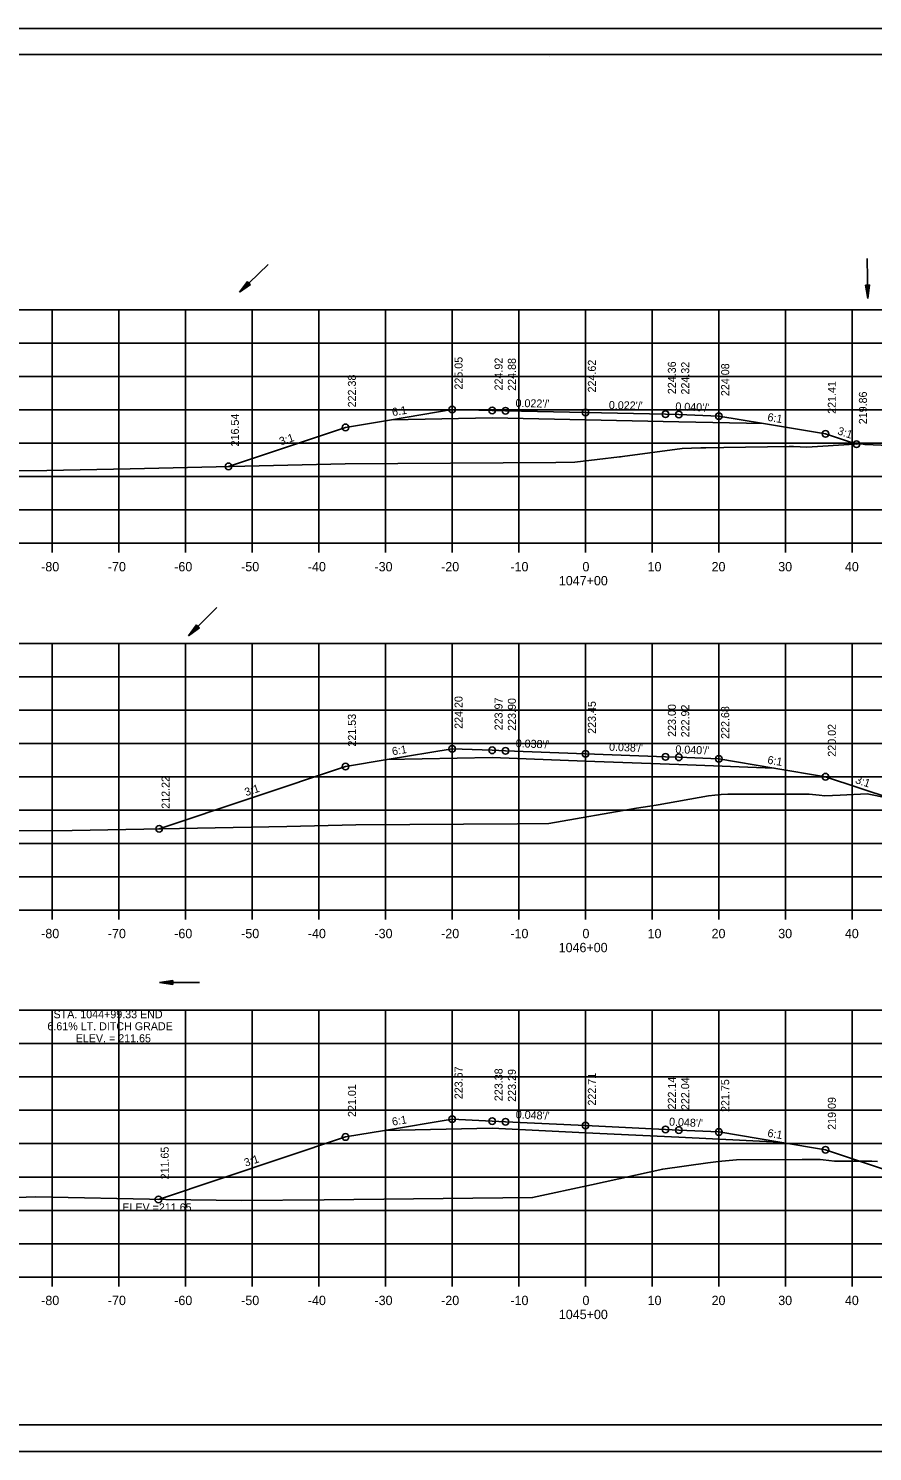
# Model space of a CAD drawing. Extents: x 1386544 to 1388153, y 379785 to 390999.
# Drawn here: x 1387276.1 to 1387402.7, y 387158.9 to 387372.2 of the extents above; entities that cross this region are included whole.
import ezdxf

# ---------------------------------------------------------------- set-up
doc = ezdxf.new("R2010")
doc.units = 0
for name, color, linetype in [('R_Alt Surface', 7, 'Continuous'), ('R_Axis', 7, 'Continuous'), ('R_Axis Annot', 7, 'Continuous'), ('R_Border', 7, 'Continuous'), ('R_Exist Surface', 7, 'Continuous'), ('R_Fin Surface', 7, 'Continuous'), ('R_Grid', 7, 'Continuous'), ('R_No Plot', 7, 'Continuous'), ('R_Water', 7, 'Continuous'), ('R_Xsect Elev', 7, 'Continuous'), ('R_Xsect Slope', 7, 'Continuous')]:
    doc.layers.add(name, color=color, linetype=linetype)

msp = doc.modelspace()

# ---------------------------------------------------------------- linework, layer by layer
at = {"layer": 'R_Alt Surface'}
for points in [[(1387330.59, 387313.54), (1387345.68, 387313.84), (1387359.68, 387313.54), (1387373.68, 387313.24), (1387386.38, 387312.97)], [(1387329.94, 387262.58), (1387345.68, 387262.9), (1387359.68, 387262.37), (1387373.68, 387261.85), (1387387.95, 387261.31)], [(1387329.51, 387206.98), (1387345.68, 387207.31), (1387359.68, 387206.63), (1387373.68, 387205.96), (1387388.81, 387205.24)]]:
    msp.add_lwpolyline(points, dxfattribs=at)
at = {"layer": 'R_Axis'}
for p, q in [((1387209.68, 387295.01), (1387509.68, 387295.01)), ((1387279.68, 387293.61), (1387279.68, 387295.01)), ((1387289.68, 387293.61), (1387289.68, 387295.01)), ((1387299.68, 387293.61), (1387299.68, 387295.01)), ((1387309.68, 387293.61), (1387309.68, 387295.01)), ((1387319.68, 387293.61), (1387319.68, 387295.01)), ((1387329.68, 387293.61), (1387329.68, 387295.01)), ((1387339.68, 387293.61), (1387339.68, 387295.01)), ((1387349.68, 387293.61), (1387349.68, 387295.01)), ((1387359.68, 387293.61), (1387359.68, 387295.01)), ((1387369.68, 387293.61), (1387369.68, 387295.01)), ((1387379.68, 387293.61), (1387379.68, 387295.01)), ((1387389.68, 387293.61), (1387389.68, 387295.01)), ((1387399.68, 387293.61), (1387399.68, 387295.01)), ((1387209.68, 387240.01), (1387509.68, 387240.01)), ((1387279.68, 387238.61), (1387279.68, 387240.01)), ((1387289.68, 387238.61), (1387289.68, 387240.01)), ((1387299.68, 387238.61), (1387299.68, 387240.01)), ((1387309.68, 387238.61), (1387309.68, 387240.01)), ((1387319.68, 387238.61), (1387319.68, 387240.01)), ((1387329.68, 387238.61), (1387329.68, 387240.01)), ((1387339.68, 387238.61), (1387339.68, 387240.01)), ((1387349.68, 387238.61), (1387349.68, 387240.01)), ((1387359.68, 387238.61), (1387359.68, 387240.01)), ((1387369.68, 387238.61), (1387369.68, 387240.01)), ((1387379.68, 387238.61), (1387379.68, 387240.01)), ((1387389.68, 387238.61), (1387389.68, 387240.01)), ((1387399.68, 387238.61), (1387399.68, 387240.01)), ((1387209.68, 387185.01), (1387509.68, 387185.01)), ((1387279.68, 387183.61), (1387279.68, 387185.01)), ((1387289.68, 387183.61), (1387289.68, 387185.01)), ((1387299.68, 387183.61), (1387299.68, 387185.01)), ((1387309.68, 387183.61), (1387309.68, 387185.01)), ((1387319.68, 387183.61), (1387319.68, 387185.01)), ((1387329.68, 387183.61), (1387329.68, 387185.01)), ((1387339.68, 387183.61), (1387339.68, 387185.01)), ((1387349.68, 387183.61), (1387349.68, 387185.01)), ((1387359.68, 387183.61), (1387359.68, 387185.01)), ((1387369.68, 387183.61), (1387369.68, 387185.01)), ((1387379.68, 387183.61), (1387379.68, 387185.01)), ((1387389.68, 387183.61), (1387389.68, 387185.01)), ((1387399.68, 387183.61), (1387399.68, 387185.01))]:
    msp.add_line(p, q, dxfattribs=at)
at = {"layer": 'R_Border'}
for p, q in [((1387201.68, 387368.3), (1387517.86, 387368.3)), ((1387354.2, 387368.04), (1387354.2, 387368.04)), ((1387354.2, 387368.04), (1387354.2, 387368.04)), ((1387517.86, 387162.84), (1387201.68, 387162.84))]:
    msp.add_line(p, q, dxfattribs=at)
at = {"layer": 'R_Exist Surface'}
for points in [[(1387209.68, 387306.78), (1387215.97, 387305.73), (1387223.93, 387305.55), (1387232.52, 387305.31), (1387252.5, 387305.63), (1387278.86, 387305.93), (1387291.37, 387306.2), (1387323.62, 387306.94), (1387355.2, 387307.15), (1387358.1, 387307.16), (1387364.79, 387307.98), (1387364.91, 387307.99), (1387365.21, 387308.03), (1387374.19, 387309.2), (1387376.96, 387309.3), (1387377.73, 387309.32), (1387380.43, 387309.37), (1387390.24, 387309.52), (1387390.88, 387309.51), (1387392.87, 387309.4), (1387400.01, 387309.85), (1387401.03, 387309.91), (1387401.59, 387309.83), (1387415.1, 387309.25)], [(1387209.68, 387257.43), (1387236.3, 387253.42), (1387247.92, 387251.89), (1387270.45, 387251.93), (1387282.69, 387251.98), (1387314.87, 387252.58), (1387325.24, 387252.83), (1387349.47, 387252.95), (1387354.16, 387253), (1387367.35, 387255.3), (1387369.31, 387255.6), (1387370.58, 387255.83), (1387378.13, 387257.15), (1387380.05, 387257.33), (1387381.02, 387257.42), (1387385.03, 387257.41), (1387393.25, 387257.4), (1387394.75, 387257.23), (1387395.58, 387257.13), (1387397.86, 387257.26), (1387401.91, 387257.46), (1387418.16, 387254.14)], [(1387271.49, 387196.83), (1387277.19, 387197.03), (1387296.74, 387196.63), (1387308.02, 387196.5), (1387320.49, 387196.59), (1387351.73, 387196.93), (1387360.56, 387198.85), (1387371.27, 387201.19), (1387378.04, 387202.15), (1387379.62, 387202.35), (1387380.14, 387202.4), (1387382.32, 387202.61), (1387392.2, 387202.63), (1387394.87, 387202.64), (1387395.35, 387202.59), (1387397.02, 387202.38), (1387402.65, 387202.37), (1387403.49, 387202.36)]]:
    msp.add_lwpolyline(points, dxfattribs=at)
at = {"layer": 'R_Fin Surface'}
for points in [[(1387306.13, 387306.54), (1387323.68, 387312.39), (1387330.59, 387313.54), (1387339.68, 387315.06), (1387345.68, 387314.93), (1387347.68, 387314.88), (1387359.68, 387314.63), (1387371.68, 387314.37), (1387373.68, 387314.32), (1387379.68, 387314.08), (1387386.38, 387312.97), (1387395.68, 387311.42), (1387400.34, 387309.86)], [(1387295.73, 387252.22), (1387323.68, 387261.54), (1387329.94, 387262.58), (1387339.68, 387264.2), (1387345.68, 387263.98), (1387347.68, 387263.9), (1387359.68, 387263.45), (1387371.68, 387263), (1387373.68, 387262.93), (1387379.68, 387262.69), (1387387.95, 387261.31), (1387395.68, 387260.02), (1387405.68, 387256.69)], [(1387295.6, 387196.65), (1387323.68, 387206.01), (1387329.51, 387206.98), (1387339.68, 387208.68), (1387345.68, 387208.39), (1387347.68, 387208.29), (1387359.68, 387207.72), (1387371.68, 387207.14), (1387373.68, 387207.05), (1387379.68, 387206.76), (1387388.81, 387205.24), (1387395.68, 387204.09), (1387411.71, 387198.75), (1387414.79, 387199.77)]]:
    msp.add_lwpolyline(points, dxfattribs=at)
at = {"layer": 'R_Grid'}
for p, q in [((1387209.68, 387330.01), (1387509.68, 387330.01)), ((1387279.68, 387295.01), (1387279.68, 387330.01)), ((1387289.68, 387295.01), (1387289.68, 387330.01)), ((1387299.68, 387295.01), (1387299.68, 387330.01)), ((1387309.68, 387295.01), (1387309.68, 387330.01)), ((1387319.68, 387295.01), (1387319.68, 387330.01)), ((1387329.68, 387295.01), (1387329.68, 387330.01)), ((1387339.68, 387295.01), (1387339.68, 387330.01)), ((1387349.68, 387295.01), (1387349.68, 387330.01)), ((1387359.68, 387295.01), (1387359.68, 387330.01)), ((1387369.68, 387295.01), (1387369.68, 387330.01)), ((1387379.68, 387295.01), (1387379.68, 387330.01)), ((1387389.68, 387295.01), (1387389.68, 387330.01)), ((1387399.68, 387295.01), (1387399.68, 387330.01)), ((1387209.68, 387325.01), (1387509.68, 387325.01)), ((1387209.68, 387320.01), (1387509.68, 387320.01)), ((1387209.68, 387315.01), (1387509.68, 387315.01)), ((1387209.68, 387310.01), (1387509.68, 387310.01)), ((1387209.68, 387305.01), (1387509.68, 387305.01)), ((1387209.68, 387300.01), (1387509.68, 387300.01)), ((1387209.68, 387295.01), (1387509.68, 387295.01)), ((1387209.68, 387280.01), (1387509.68, 387280.01)), ((1387279.68, 387240.01), (1387279.68, 387280.01)), ((1387289.68, 387240.01), (1387289.68, 387280.01)), ((1387299.68, 387240.01), (1387299.68, 387280.01)), ((1387309.68, 387240.01), (1387309.68, 387280.01)), ((1387319.68, 387240.01), (1387319.68, 387280.01)), ((1387329.68, 387240.01), (1387329.68, 387280.01)), ((1387339.68, 387240.01), (1387339.68, 387280.01)), ((1387349.68, 387240.01), (1387349.68, 387280.01)), ((1387359.68, 387240.01), (1387359.68, 387280.01)), ((1387369.68, 387240.01), (1387369.68, 387280.01)), ((1387379.68, 387240.01), (1387379.68, 387280.01)), ((1387389.68, 387240.01), (1387389.68, 387280.01)), ((1387399.68, 387240.01), (1387399.68, 387280.01)), ((1387209.68, 387275.01), (1387509.68, 387275.01)), ((1387209.68, 387270.01), (1387509.68, 387270.01)), ((1387209.68, 387265.01), (1387509.68, 387265.01)), ((1387209.68, 387260.01), (1387509.68, 387260.01)), ((1387209.68, 387255.01), (1387509.68, 387255.01)), ((1387209.68, 387250.01), (1387509.68, 387250.01)), ((1387209.68, 387245.01), (1387509.68, 387245.01)), ((1387209.68, 387240.01), (1387509.68, 387240.01)), ((1387209.68, 387225.01), (1387509.68, 387225.01)), ((1387279.68, 387185.01), (1387279.68, 387225.01)), ((1387289.68, 387185.01), (1387289.68, 387225.01)), ((1387299.68, 387185.01), (1387299.68, 387225.01)), ((1387309.68, 387185.01), (1387309.68, 387225.01)), ((1387319.68, 387185.01), (1387319.68, 387225.01)), ((1387329.68, 387185.01), (1387329.68, 387225.01)), ((1387339.68, 387185.01), (1387339.68, 387225.01)), ((1387349.68, 387185.01), (1387349.68, 387225.01)), ((1387359.68, 387185.01), (1387359.68, 387225.01)), ((1387369.68, 387185.01), (1387369.68, 387225.01)), ((1387379.68, 387185.01), (1387379.68, 387225.01)), ((1387389.68, 387185.01), (1387389.68, 387225.01)), ((1387399.68, 387185.01), (1387399.68, 387225.01)), ((1387209.68, 387220.01), (1387509.68, 387220.01)), ((1387209.68, 387215.01), (1387509.68, 387215.01)), ((1387209.68, 387210.01), (1387509.68, 387210.01)), ((1387209.68, 387205.01), (1387509.68, 387205.01)), ((1387209.68, 387200.01), (1387509.68, 387200.01)), ((1387209.68, 387195.01), (1387509.68, 387195.01)), ((1387209.68, 387190.01), (1387509.68, 387190.01)), ((1387209.68, 387185.01), (1387509.68, 387185.01))]:
    msp.add_line(p, q, dxfattribs=at)
at = {"layer": 'R_No Plot'}
for p, q in [((1387189.28, 387372.19), (1387522.61, 387372.19)), ((1387189.28, 387158.86), (1387522.61, 387158.86))]:
    msp.add_line(p, q, dxfattribs=at)
for points in [[(1387189.27, 387372.19), (1387522.61, 387372.19), (1387522.61, 387158.86), (1387189.27, 387158.86)], [(1387435.6, 387368.3), (1387455.22, 387368.3), (1387455.22, 387358.42), (1387471.33, 387358.42), (1387494.53, 387358.42), (1387494.53, 387334.09), (1387517.86, 387334.09), (1387517.86, 387162.84), (1387201.68, 387162.84), (1387201.68, 387368.3)]]:
    msp.add_lwpolyline(points, close=True, dxfattribs=at)
for centre in [(1387339.68, 387315.06), (1387345.68, 387314.93), (1387347.68, 387314.88), (1387359.68, 387314.63), (1387371.68, 387314.37), (1387373.68, 387314.32), (1387379.68, 387314.08), (1387323.68, 387312.39), (1387395.68, 387311.42), (1387400.34, 387309.86), (1387306.13, 387306.54), (1387339.68, 387264.2), (1387345.68, 387263.98), (1387347.68, 387263.9), (1387359.68, 387263.45), (1387371.68, 387263), (1387373.68, 387262.93), (1387323.68, 387261.54), (1387379.68, 387262.69), (1387395.68, 387260.02), (1387295.73, 387252.22), (1387339.68, 387208.68), (1387345.68, 387208.39), (1387347.68, 387208.29), (1387359.68, 387207.72), (1387323.68, 387206.01), (1387371.68, 387207.14), (1387373.68, 387207.05), (1387379.68, 387206.76), (1387395.68, 387204.09), (1387295.6, 387196.65), (1387295.6, 387196.65)]:
    msp.add_circle(centre, 0.5, dxfattribs=at)
at = {"layer": 'R_Water'}
for p, q in [((1387312.07, 387336.82), (1387307.76, 387332.64)), ((1387401.92, 387337.73), (1387402.03, 387331.73)), ((1387308.99, 387334.25), (1387307.76, 387332.64)), ((1387308.99, 387334.25), (1387307.76, 387332.64)), ((1387309.4, 387333.82), (1387307.76, 387332.64)), ((1387309.4, 387333.82), (1387307.76, 387332.64)), ((1387309.02, 387334.22), (1387308, 387332.88)), ((1387309.02, 387334.22), (1387308, 387332.88)), ((1387309.37, 387333.86), (1387308, 387332.88)), ((1387309.37, 387333.86), (1387308, 387332.88)), ((1387309.06, 387334.18), (1387308.24, 387333.12)), ((1387309.06, 387334.18), (1387308.24, 387333.12)), ((1387309.33, 387333.89), (1387308.24, 387333.12)), ((1387309.33, 387333.89), (1387308.24, 387333.12)), ((1387309.09, 387334.14), (1387308.48, 387333.35)), ((1387309.09, 387334.14), (1387308.48, 387333.35)), ((1387309.3, 387333.93), (1387308.48, 387333.35)), ((1387309.3, 387333.93), (1387308.48, 387333.35)), ((1387309.13, 387334.11), (1387308.73, 387333.58)), ((1387309.13, 387334.11), (1387308.73, 387333.58)), ((1387309.26, 387333.97), (1387308.73, 387333.58)), ((1387309.26, 387333.97), (1387308.73, 387333.58)), ((1387309.16, 387334.07), (1387308.97, 387333.82)), ((1387309.16, 387334.07), (1387308.97, 387333.82)), ((1387309.23, 387334), (1387308.97, 387333.82)), ((1387309.23, 387334), (1387308.97, 387333.82)), ((1387309.4, 387333.82), (1387308.99, 387334.25)), ((1387309.4, 387333.82), (1387308.99, 387334.25)), ((1387402.29, 387333.74), (1387401.69, 387333.73)), ((1387402.29, 387333.74), (1387401.69, 387333.73)), ((1387401.69, 387333.73), (1387402.03, 387331.73)), ((1387401.69, 387333.73), (1387402.03, 387331.73)), ((1387401.74, 387333.73), (1387402.02, 387332.07)), ((1387401.74, 387333.73), (1387402.02, 387332.07)), ((1387401.79, 387333.73), (1387402.02, 387332.41)), ((1387401.79, 387333.73), (1387402.02, 387332.41)), ((1387401.84, 387333.73), (1387402.01, 387332.74)), ((1387401.84, 387333.73), (1387402.01, 387332.74)), ((1387401.89, 387333.73), (1387402, 387333.08)), ((1387401.89, 387333.73), (1387402, 387333.08)), ((1387401.95, 387333.73), (1387402, 387333.41)), ((1387401.95, 387333.73), (1387402, 387333.41)), ((1387402.09, 387333.73), (1387402, 387333.08)), ((1387402.04, 387333.73), (1387402, 387333.41)), ((1387402.09, 387333.73), (1387402, 387333.08)), ((1387402.04, 387333.73), (1387402, 387333.41)), ((1387402.14, 387333.73), (1387402.01, 387332.74)), ((1387402.14, 387333.73), (1387402.01, 387332.74)), ((1387402.24, 387333.74), (1387402.02, 387332.07)), ((1387402.24, 387333.74), (1387402.02, 387332.07)), ((1387402.19, 387333.73), (1387402.02, 387332.41)), ((1387402.19, 387333.73), (1387402.02, 387332.41)), ((1387402.29, 387333.74), (1387402.03, 387331.73)), ((1387402.29, 387333.74), (1387402.03, 387331.73)), ((1387304.38, 387285.37), (1387300.11, 387281.15)), ((1387301.33, 387282.77), (1387300.11, 387281.15)), ((1387301.33, 387282.77), (1387300.11, 387281.15)), ((1387301.36, 387282.73), (1387300.35, 387281.39)), ((1387301.36, 387282.73), (1387300.35, 387281.39)), ((1387301.4, 387282.7), (1387300.59, 387281.63)), ((1387301.4, 387282.7), (1387300.59, 387281.63)), ((1387301.68, 387282.41), (1387300.59, 387281.63)), ((1387301.68, 387282.41), (1387300.59, 387281.63)), ((1387301.43, 387282.66), (1387300.83, 387281.86)), ((1387301.43, 387282.66), (1387300.83, 387281.86)), ((1387301.64, 387282.45), (1387300.83, 387281.86)), ((1387301.64, 387282.45), (1387300.83, 387281.86)), ((1387301.47, 387282.63), (1387301.07, 387282.1)), ((1387301.47, 387282.63), (1387301.07, 387282.1)), ((1387301.6, 387282.49), (1387301.07, 387282.1)), ((1387301.6, 387282.49), (1387301.07, 387282.1)), ((1387301.5, 387282.59), (1387301.31, 387282.33)), ((1387301.5, 387282.59), (1387301.31, 387282.33)), ((1387301.57, 387282.52), (1387301.31, 387282.33)), ((1387301.57, 387282.52), (1387301.31, 387282.33)), ((1387301.75, 387282.34), (1387301.33, 387282.77)), ((1387301.75, 387282.34), (1387301.33, 387282.77)), ((1387301.75, 387282.34), (1387300.11, 387281.15)), ((1387301.75, 387282.34), (1387300.11, 387281.15)), ((1387301.71, 387282.38), (1387300.35, 387281.39)), ((1387301.71, 387282.38), (1387300.35, 387281.39)), ((1387297.78, 387229.45), (1387295.78, 387229.15)), ((1387297.78, 387229.45), (1387295.78, 387229.15)), ((1387301.78, 387229.15), (1387295.78, 387229.15)), ((1387297.78, 387228.85), (1387295.78, 387229.15)), ((1387297.78, 387228.85), (1387295.78, 387229.15)), ((1387297.78, 387229.4), (1387296.11, 387229.15)), ((1387297.78, 387229.4), (1387296.11, 387229.15)), ((1387297.78, 387228.9), (1387296.11, 387229.15)), ((1387297.78, 387228.9), (1387296.11, 387229.15)), ((1387297.78, 387229.35), (1387296.46, 387229.15)), ((1387297.78, 387229.35), (1387296.46, 387229.15)), ((1387297.78, 387228.96), (1387296.46, 387229.15)), ((1387297.78, 387228.96), (1387296.46, 387229.15)), ((1387297.78, 387229.3), (1387296.79, 387229.15)), ((1387297.78, 387229.3), (1387296.79, 387229.15)), ((1387297.78, 387229.01), (1387296.79, 387229.15)), ((1387297.78, 387229.01), (1387296.79, 387229.15)), ((1387297.78, 387229.25), (1387297.13, 387229.15)), ((1387297.78, 387229.25), (1387297.13, 387229.15)), ((1387297.78, 387229.06), (1387297.13, 387229.15)), ((1387297.78, 387229.06), (1387297.13, 387229.15)), ((1387297.78, 387229.2), (1387297.46, 387229.15)), ((1387297.78, 387229.2), (1387297.46, 387229.15)), ((1387297.78, 387229.11), (1387297.46, 387229.15)), ((1387297.78, 387229.11), (1387297.46, 387229.15)), ((1387297.78, 387228.85), (1387297.78, 387229.45)), ((1387297.78, 387228.85), (1387297.78, 387229.45))]:
    msp.add_line(p, q, dxfattribs=at)

# ---------------------------------------------------------------- texts
at = {"layer": 'R_Axis Annot'}
for s, p in [('-80', (1387278.02, 387290.81)), ('-70', (1387288.02, 387290.81)), ('-60', (1387297.98, 387290.81)), ('-50', (1387308.02, 387290.81)), ('-40', (1387318.02, 387290.81)), ('-30', (1387328.02, 387290.81)), ('-20', (1387338.02, 387290.81)), ('-10', (1387348.41, 387290.81)), ('0', (1387359.22, 387290.81)), ('10', (1387368.99, 387290.81)), ('20', (1387378.59, 387290.81)), ('30', (1387388.59, 387290.81)), ('40', (1387398.59, 387290.81)), ('1047+00', (1387355.68, 387288.71)), ('-80', (1387278.02, 387235.81)), ('-70', (1387288.02, 387235.81)), ('-60', (1387297.98, 387235.81)), ('-50', (1387308.02, 387235.81)), ('-40', (1387318.02, 387235.81)), ('-30', (1387328.02, 387235.81)), ('-20', (1387338.02, 387235.81)), ('-10', (1387348.41, 387235.81)), ('0', (1387359.22, 387235.81)), ('10', (1387368.99, 387235.81)), ('20', (1387378.59, 387235.81)), ('30', (1387388.59, 387235.81)), ('40', (1387398.59, 387235.81)), ('1046+00', (1387355.65, 387233.71)), ('-80', (1387278.02, 387180.81)), ('-70', (1387288.02, 387180.81)), ('-60', (1387297.98, 387180.81)), ('-50', (1387308.02, 387180.81)), ('-40', (1387318.02, 387180.81)), ('-30', (1387328.02, 387180.81)), ('-20', (1387338.02, 387180.81)), ('-10', (1387348.41, 387180.81)), ('0', (1387359.22, 387180.81)), ('10', (1387368.99, 387180.81)), ('20', (1387378.59, 387180.81)), ('30', (1387388.59, 387180.81)), ('40', (1387398.59, 387180.81)), ('1045+00', (1387355.68, 387178.71))]:
    msp.add_text(s, height=1.4, dxfattribs=at).set_placement(p)
at = {"layer": 'R_Xsect Elev'}
for s, p in [('225.05', (1387341.23, 387318.06)), ('224.92', (1387347.23, 387317.93)), ('224.88', (1387349.23, 387317.88)), ('224.62', (1387361.23, 387317.63)), ('224.36', (1387373.23, 387317.37)), ('224.32', (1387375.23, 387317.32)), ('224.08', (1387381.23, 387317.08)), ('222.38', (1387325.23, 387315.39)), ('221.41', (1387397.23, 387314.42)), ('219.86', (1387401.89, 387312.86)), ('216.54', (1387307.68, 387309.54)), ('224.20', (1387341.23, 387267.2)), ('223.97', (1387347.23, 387266.98)), ('223.90', (1387349.23, 387266.9)), ('223.45', (1387361.23, 387266.45)), ('223.00', (1387373.23, 387266)), ('222.92', (1387375.23, 387265.93)), ('222.68', (1387381.23, 387265.69)), ('221.53', (1387325.23, 387264.54)), ('220.02', (1387397.23, 387263.02)), ('212.22', (1387297.28, 387255.22)), ('223.67', (1387341.23, 387211.68)), ('223.38', (1387347.23, 387211.39)), ('223.29', (1387349.23, 387211.29)), ('222.71', (1387361.23, 387210.72)), ('222.14', (1387373.23, 387210.14)), ('222.04', (1387375.23, 387210.05)), ('221.75', (1387381.23, 387209.76)), ('221.01', (1387325.23, 387209.01)), ('219.09', (1387397.23, 387207.09)), ('211.65', (1387297.15, 387199.65))]:
    msp.add_text(s, height=1.2, rotation=90, dxfattribs=at).set_placement(p)
for s, p in [('STA. 1044+99.33 END ', (1387279.87, 387223.81)), ('6.61% LT. DITCH GRADE', (1387278.95, 387222.01)), ('ELEV. = 211.65', (1387283.2, 387220.21)), ('ELEV.=211.65', (1387290.19, 387194.86))]:
    msp.add_text(s, height=1.2, dxfattribs=at).set_placement(p)
at = {"layer": 'R_Xsect Slope'}
for s, rotation, p in [("0.022'/'", 358.7676, (1387349.17, 387315.45)), ('6:1', 9.4623, (1387330.75, 387314.07)), ("0.022'/'", 358.7676, (1387363.17, 387315.15)), ("0.040'/'", 357.7094, (1387373.14, 387314.95)), ('6:1', 350.5377, (1387386.91, 387313.39)), ('3:1', 341.5651, (1387397.38, 387311.38)), ('3:1', 18.4349, (1387313.96, 387309.68)), ("0.038'/'", 357.8517, (1387349.19, 387264.45)), ('6:1', 9.4623, (1387330.75, 387263.22)), ("0.038'/'", 357.8517, (1387363.19, 387263.92)), ("0.040'/'", 357.7094, (1387373.14, 387263.55)), ('6:1', 350.5377, (1387386.91, 387261.99)), ('3:1', 341.5651, (1387400.05, 387259.09)), ('3:1', 18.4349, (1387308.76, 387257.09)), ("0.048'/'", 357.2519, (1387349.19, 387208.82)), ('6:1', 9.4623, (1387330.75, 387207.7)), ("0.048'/'", 357.2519, (1387372.19, 387207.72)), ('6:1', 350.5377, (1387386.91, 387206.06)), ('3:1', 18.4349, (1387308.69, 387201.54))]:
    msp.add_text(s, height=1.2, rotation=rotation, dxfattribs=at).set_placement(p)

doc.saveas('drawing.dxf')
